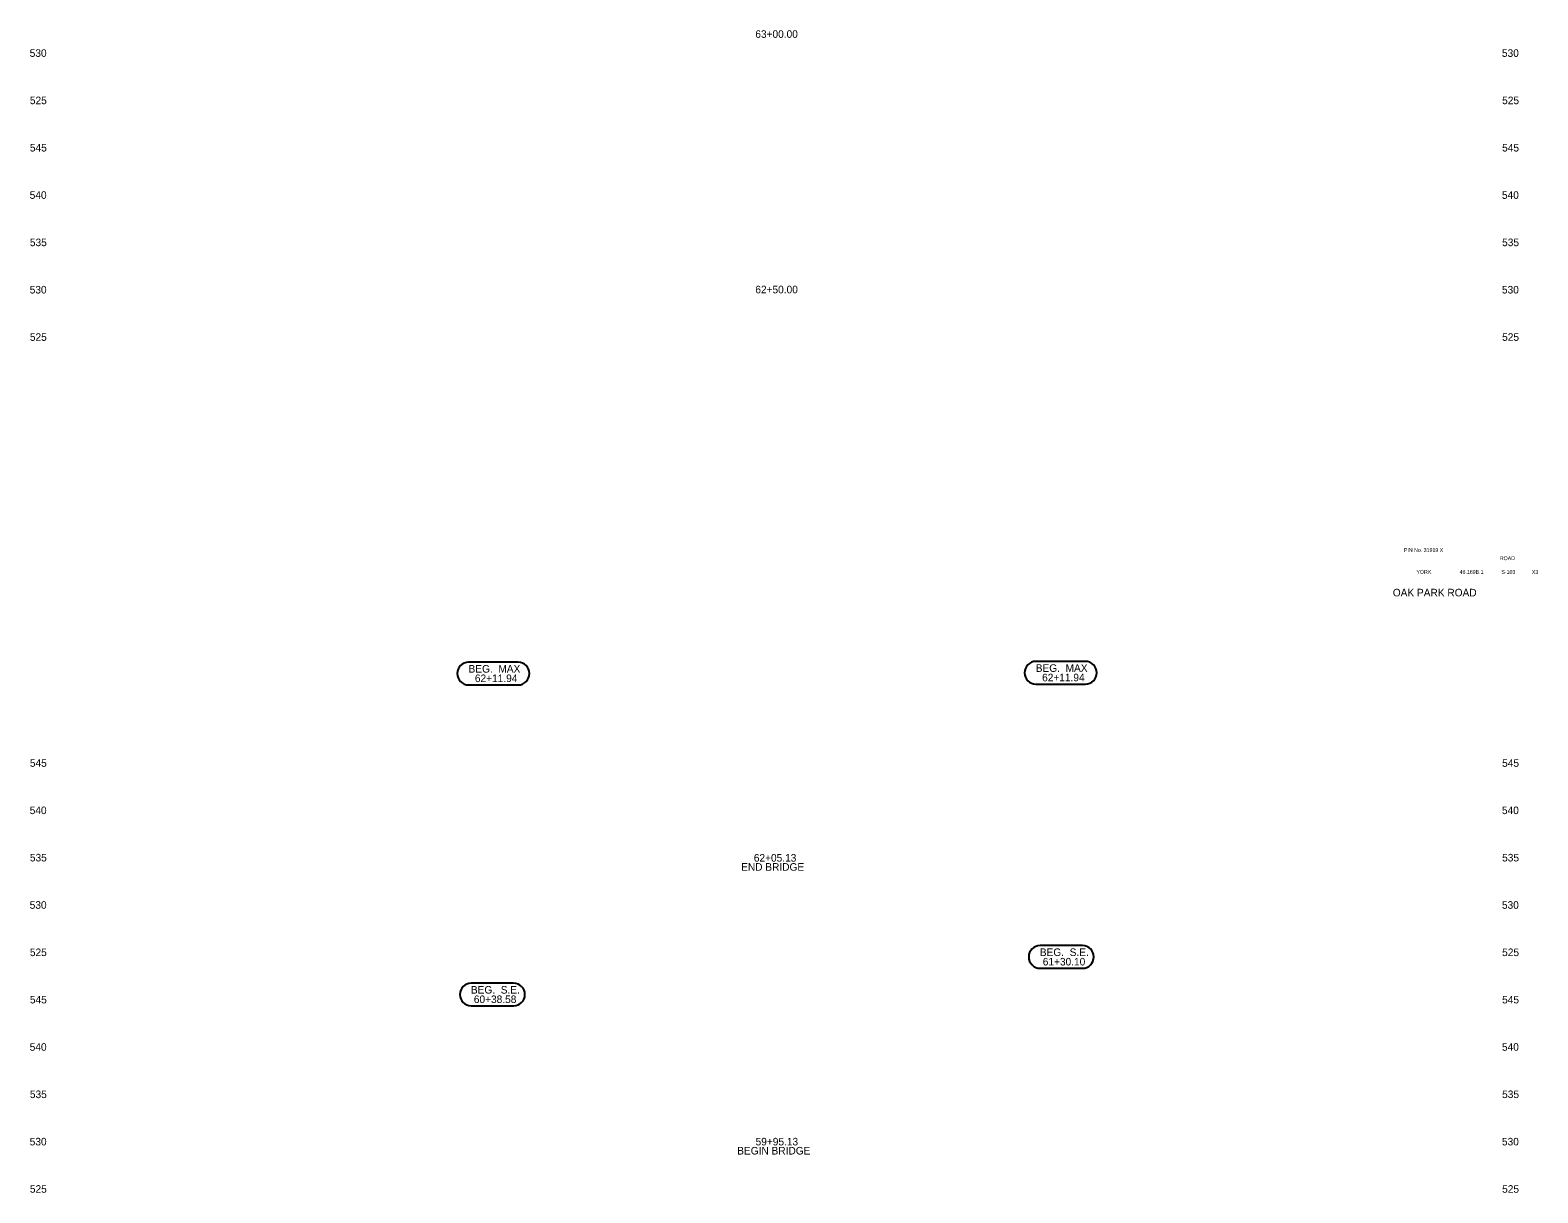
# Model space of a CAD drawing. Extents: x 1001 to 1160, y 1010 to 2023.
# Drawn here: x 1001.2 to 1160.4, y 1265.1 to 1387.9 of the extents above; entities that cross this region are included whole.
import ezdxf

# ---------------------------------------------------------------- set-up
doc = ezdxf.new("R2010")
doc.units = 0
for name, color, linetype in [('RD_SHT_TX', 7, 'Continuous'), ('RD_XS_TX_Elev_EX', 7, 'Continuous'), ('RD_XS_TX_Misc', 7, 'Continuous'), ('RD_XS_TX_Notes', 7, 'Continuous'), ('RD_XS_TX_Station', 7, 'Continuous')]:
    doc.layers.add(name, color=color, linetype=linetype)

msp = doc.modelspace()

# ---------------------------------------------------------------- linework, layer by layer
at = {"layer": 'RD_XS_TX_Misc'}
for p, q in [((1052.71, 1321.15), (1047.49, 1321.15)), ((1112.63, 1321.23), (1107.4, 1321.23)), ((1047.49, 1318.75), (1052.71, 1318.75)), ((1107.4, 1318.83), (1112.63, 1318.83))]:
    msp.add_line(p, q, dxfattribs=at)
for centre, start, end in [((1047.49, 1319.95), 90, 270), ((1052.71, 1319.95), 270, 90), ((1107.4, 1320.03), 90, 270), ((1112.63, 1320.03), 270, 90)]:
    msp.add_arc(centre, 1.2, start, end, dxfattribs=at)
at = {"layer": 'RD_XS_TX_Notes'}
for p, q in [((1112.32, 1291.21), (1107.85, 1291.21)), ((1107.85, 1288.81), (1112.32, 1288.81)), ((1052.24, 1287.24), (1047.76, 1287.24)), ((1047.76, 1284.84), (1052.24, 1284.84))]:
    msp.add_line(p, q, dxfattribs=at)
for centre, start, end in [((1107.85, 1290.01), 90, 270), ((1112.32, 1290.01), 270, 90), ((1047.76, 1286.04), 90, 270), ((1052.24, 1286.04), 270, 90)]:
    msp.add_arc(centre, 1.2, start, end, dxfattribs=at)

# ---------------------------------------------------------------- texts
at = {"layer": 'RD_SHT_TX'}
for s, height, p in [('PIN No. 31919 X', 0.4, (1146.28, 1332.8)), ('ROAD', 0.4, (1156.41, 1331.93)), ('YORK', 0.4, (1147.6, 1330.48)), ('46.169B.1', 0.4, (1152.16, 1330.48)), ('S-103', 0.4, (1156.57, 1330.48)), ('X3', 0.4, (1159.79, 1330.48)), ('OAK PARK ROAD', 0.8, (1145.1, 1328.1))]:
    msp.add_text(s, height=height, dxfattribs=at).set_placement(p)
at = {"layer": 'RD_XS_TX_Elev_EX'}
for s, p in [('530', (1001.13, 1385.1)), ('530', (1156.63, 1385.1)), ('525', (1001.15, 1380.1)), ('525', (1156.65, 1380.1)), ('545', (1001.15, 1375.1)), ('545', (1156.65, 1375.1)), ('540', (1001.13, 1370.1)), ('540', (1156.63, 1370.1)), ('535', (1001.15, 1365.1)), ('535', (1156.65, 1365.1)), ('530', (1001.13, 1360.1)), ('530', (1156.63, 1360.1)), ('525', (1001.15, 1355.1)), ('525', (1156.65, 1355.1)), ('545', (1001.15, 1310.1)), ('545', (1156.65, 1310.1)), ('540', (1001.13, 1305.1)), ('540', (1156.63, 1305.1)), ('535', (1001.15, 1300.1)), ('535', (1156.65, 1300.1)), ('530', (1001.13, 1295.1)), ('530', (1156.63, 1295.1)), ('525', (1001.15, 1290.1)), ('525', (1156.65, 1290.1)), ('545', (1001.15, 1285.1)), ('545', (1156.65, 1285.1)), ('540', (1001.13, 1280.1)), ('540', (1156.63, 1280.1)), ('535', (1001.15, 1275.1)), ('535', (1156.65, 1275.1)), ('530', (1001.13, 1270.1)), ('530', (1156.63, 1270.1)), ('525', (1001.15, 1265.1)), ('525', (1156.65, 1265.1))]:
    msp.add_text(s, height=0.8, dxfattribs=at).set_placement(p)
at = {"layer": 'RD_XS_TX_Notes'}
for s, p in [('BEG.  MAX', (1047.48, 1320.05)), ('BEG.  MAX', (1107.39, 1320.13)), ('62+11.94', (1048.15, 1319.05)), ('62+11.94', (1108.06, 1319.13)), ('BEG.  S.E.', (1107.82, 1290.11)), ('61+30.10', (1108.13, 1289.11)), ('BEG.  S.E.', (1047.73, 1286.14)), ('60+38.58', (1048.04, 1285.14))]:
    msp.add_text(s, height=0.8, dxfattribs=at).set_placement(p)
at = {"layer": 'RD_XS_TX_Station'}
for s, p in [('63+00.00', (1077.77, 1387.11)), ('62+50.00', (1077.77, 1360.12)), ('END BRIDGE', (1076.27, 1299.12)), ('62+05.13', (1077.61, 1300.08)), ('59+95.13', (1077.8, 1270.1)), ('BEGIN BRIDGE', (1075.86, 1269.14))]:
    msp.add_text(s, height=0.8, dxfattribs=at).set_placement(p)

doc.saveas('drawing.dxf')
